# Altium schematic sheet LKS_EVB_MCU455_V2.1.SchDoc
size A3; SheetNumber: 1; SheetTotal: 1
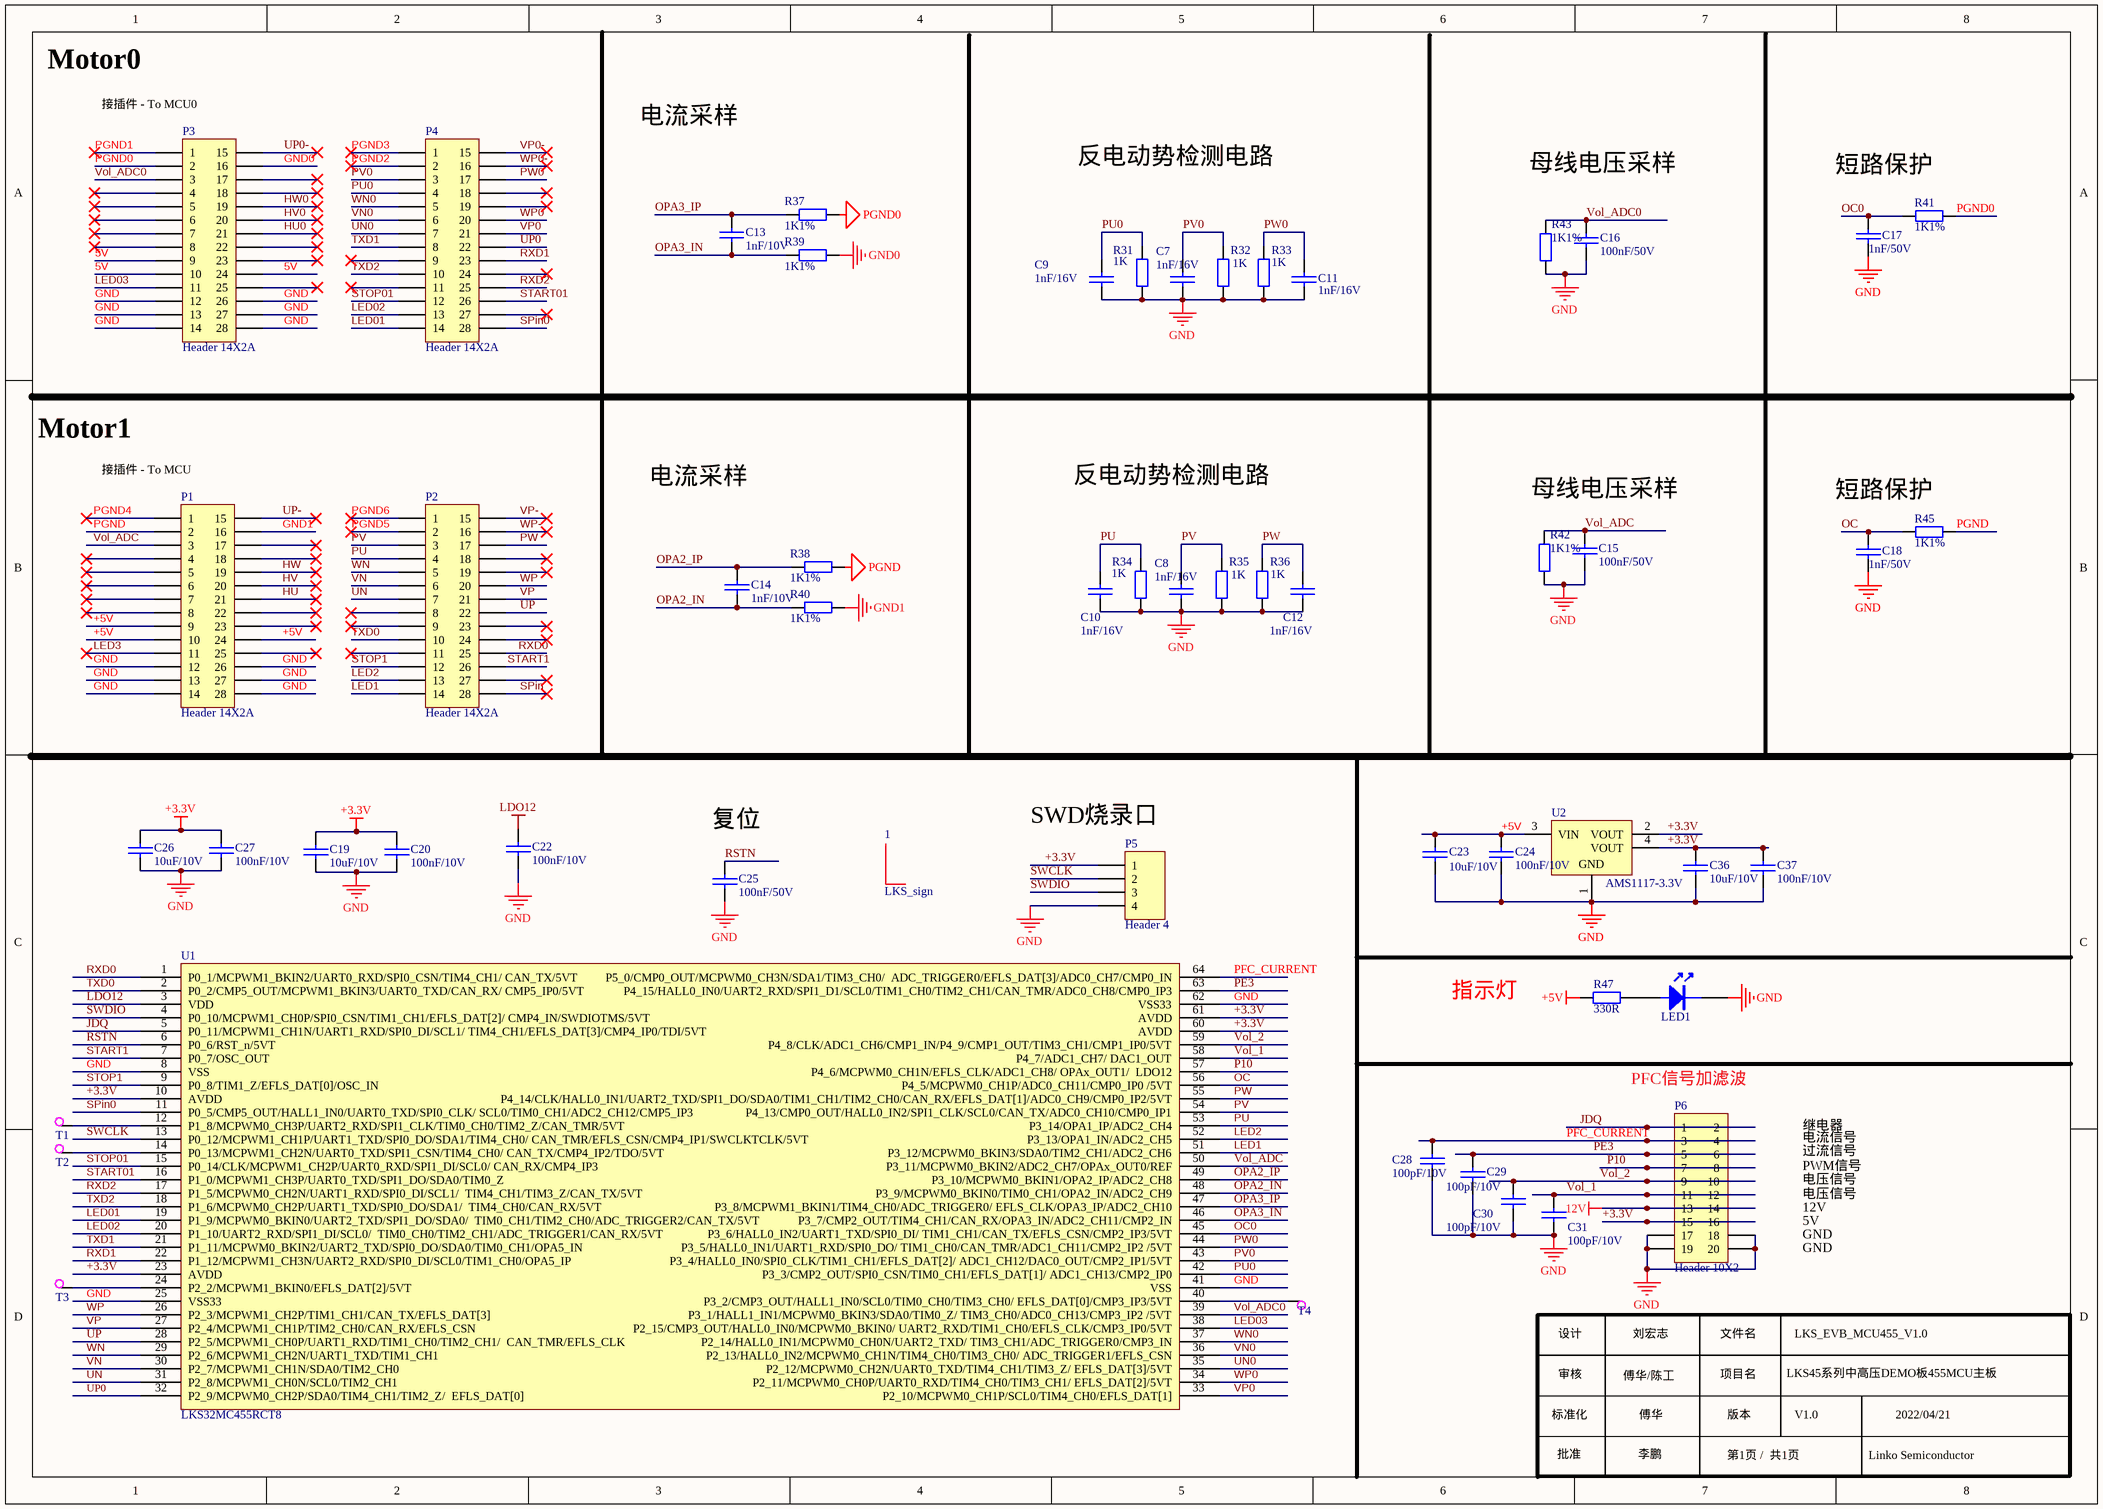
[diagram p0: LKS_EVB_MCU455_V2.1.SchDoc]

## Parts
1  LKS_sign  [LKS_LOGO2]
C7  1nF/16V  [0603C]
C8  1nF/16V  [0603C]
C9  1nF/16V  [0603C]
C10  1nF/16V  [0603C]
C11  1nF/16V  [0603C]
C12  1nF/16V  [0603C]
C13  1nF/10V  [0603C]
C14  1nF/10V  [0603C]
C15  100nF/50V  [0603C]
C16  100nF/50V  [0603C]
C17  1nF/50V  [0603C]
C18  1nF/50V  [0603C]
C19  10uF/10V  [0603C]
C20  100nF/10V  [0603C]
C22  100nF/10V  [0603C]
C23  10uF/10V  [0603C]
C24  100nF/10V  [0603C]
C25  100nF/50V  [0603C]
C26  10uF/10V  [0603C]
C27  100nF/10V  [0603C]
C28  100pF/10V  [0603C]
C29  100pF/10V  [0603C]
C30  100pF/10V  [0603C]
C31  100pF/10V  [0603C]
C36  10uF/10V  [0603C]
C37  100nF/10V  [0603C]
LED1  LED  [LED_0805R]  (value not drawn)
P1  Header 14X2A  [HDR2X14_CEN]
P2  Header 14X2A  [HDR2X14_CEN]
P3  Header 14X2A  [HDR2X14_CEN]
P4  Header 14X2A  [HDR2X14_CEN]
P5  Header 4  [HDR1X4]
P6  Header 10X2  [HDR2X10]
R31  1K  [0603R]
R32  1K  [0603R]
R33  1K  [0603R]
R34  1K  [0603R]
R35  1K  [0603R]
R36  1K  [0603R]
R37  1K1%  [0603R]
R38  1K1%  [0603R]
R39  1K1%  [0603R]
R40  1K1%  [0603R]
R41  1K1%  [0603R]
R42  1K1%  [0603R]
R43  1K1%  [0603R]
R45  1K1%  [0603R]
R47  330R  [0603R]
T1  TestP  [TP-40]  (value not drawn)
T2  TestP  [TP-40]  (value not drawn)
T3  TestP  [TP-40]  (value not drawn)
T4  TestP  [TP-40]  (value not drawn)
U1  LKS32MC455RCT8  [LQFP64]
U2  AMS1117-3.3V  [DCY0004A_M]

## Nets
12V: P6.13 P6.14
+3.3V: C19.1 C20.1 C26.1 C27.1 C36.1 C37.1 P5.1 P6.15 P6.16 U1.10(AVDD) U1.23(AVDD) U1.60(AVDD) U1.61(AVDD) U2.2(VOUT) U2.4(VOUT)
+5V: C23.1 C24.1 P1.9 P1.10 P1.24 R47.1 U2.3(VIN)
GND: C7.2 C8.2 C9.2 C10.2 C11.2 C12.2 C15.1 C16.1 C17.1 C18.1 C19.2 C20.2 C22.2 C23.2 C24.2 C25.2 C26.2 C27.2 C28.2 C29.2 C30.2 C31.2 C36.2 C37.2 LED1.2(K) P1.12 P1.13 P1.14 P1.26 P1.27 P1.28 P3.12 P3.13 P3.14 P3.26 P3.27 P3.28 P5.4 P6.17 P6.18 P6.19 P6.20 R31.2 R32.2 R33.2 R34.2 R35.2 R36.2 R42.1 R43.1 U1.8(VSS) U1.25(VSS33) U1.41(VSS) U1.62(VSS33) U2.1(GND)
GND0: P3.16 R39.1
GND1: P1.16 R40.1
LDO12: C22.1 U1.3(VDD)
PGND: P1.2 R38.1 R45.2
PGND0: P3.2 R37.1 R41.2
5V: P3.9 P3.10 P3.24
HU: P1.21
HU0: P3.21
HV: P1.20
HV0: P3.20
HW: P1.19
HW0: P3.19
JDQ: P6.1 P6.2 U1.5(P0_11/MCPWM1_CH1N/UART1_RXD/SPI0_DI/SCL1/_TIM4_CH1/EFLS_DAT[3]/CMP4_IP0/TDI/5VT)
LED01: P4.14 U1.19(P1_9/MCPWM0_BKIN0/UART2_TXD/SPI1_DO/SDA0/__TIM0_CH1/TIM2_CH0/ADC_TRIGGER2/CAN_TX/5VT)
LED1: P2.14 U1.51(P3_12/MCPWM0_BKIN3/SDA0/TIM2_CH1/ADC2_CH6)
LED02: P4.13 U1.20(P1_10/UART2_RXD/SPI1_DI/SCL0/__TIM0_CH0/TIM2_CH1/ADC_TRIGGER1/CAN_RX/5VT)
LED2: P2.13 U1.52(P3_13/OPA1_IN/ADC2_CH5)
LED03: P3.11 U1.38(P2_15/CMP3_OUT/HALL0_IN0/MCPWM0_BKIN0/_UART2_RXD/TIM1_CH0/EFLS_CLK/CMP3_IP0/5VT)
LED3: P1.11
OC: C18.2 R45.1 U1.56(P4_5/MCPWM0_CH1P/ADC0_CH11/CMP0_IP0_/5VT)
OC0: C17.2 R41.1 U1.45(P3_6/HALL0_IN2/UART1_TXD/SPI0_DI/_TIM1_CH1/CAN_TX/EFLS_CSN/CMP2_IP3/5VT)
OPA2_IN: C14.2 R40.2 U1.48(P3_9/MCPWM0_BKIN0/TIM0_CH1/OPA2_IN/ADC2_CH9)
OPA2_IP: C14.1 R38.2 U1.49(P3_10/MCPWM0_BKIN1/OPA2_IP/ADC2_CH8)
OPA3_IN: C13.2 R39.2 U1.46(P3_7/CMP2_OUT/TIM4_CH1/CAN_RX/OPA3_IN/ADC2_CH11/CMP2_IN)
OPA3_IP: C13.1 R37.2 U1.47(P3_8/MCPWM1_BKIN1/TIM4_CH0/ADC_TRIGGER0/_EFLS_CLK/OPA3_IP/ADC2_CH10)
P10: P6.7 P6.8 U1.57(P4_6/MCPWM0_CH1N/EFLS_CLK/ADC1_CH8/_OPAx_OUT1/__LDO12)
PE3: C29.1 P6.5 P6.6 U1.63(P4_15/HALL0_IN0/UART2_RXD/SPI1_D1/SCL0/TIM1_CH0/TIM2_CH1/CAN_TMR/ADC0_CH8/CMP0_IP3)
PFC_CURRENT: C28.1 P6.3 P6.4 U1.64(P5_0/CMP0_OUT/MCPWM0_CH3N/SDA1/TIM3_CH0/__ADC_TRIGGER0/EFLS_DAT[3]/ADC0_CH7/CMP0_IN)
PGND1: P3.1
PGND2: P4.2
PGND3: P4.1
PGND4: P1.1
PGND5: P2.2
PGND6: P2.1
PU: C10.1 P2.4 R34.1 U1.53(P3_14/OPA1_IP/ADC2_CH4)
PU0: C9.1 P4.4 R31.1 U1.42(P3_3/CMP2_OUT/SPI0_CSN/TIM0_CH1/EFLS_DAT[1]/_ADC1_CH13/CMP2_IP0)
PV: C8.1 P2.3 R35.1 U1.54(P4_13/CMP0_OUT/HALL0_IN2/SPI1_CLK/SCL0/CAN_TX/ADC0_CH10/CMP0_IP1)
PV0: C7.1 P4.3 R32.1 U1.43(P3_4/HALL0_IN0/SPI0_CLK/TIM1_CH1/EFLS_DAT[2]/_ADC1_CH12/DAC0_OUT/CMP2_IP1/5VT)
PW: C12.1 P2.17 R36.1 U1.55(P4_14/CLK/HALL0_IN1/UART2_TXD/SPI1_DO/SDA0/TIM1_CH1/TIM2_CH0/CAN_RX/EFLS_DAT[1]/ADC0_CH9/CMP0_IP2/5VT)
PW0: C11.1 P4.17 R33.1 U1.44(P3_5/HALL0_IN1/UART1_RXD/SPI0_DO/_TIM1_CH0/CAN_TMR/ADC1_CH11/CMP2_IP2_/5VT)
RSTN: C25.1 U1.6(P0_6/RST_n/5VT)
RXD0: P2.25 U1.1(P0_1/MCPWM1_BKIN2/UART0_RXD/SPI0_CSN/TIM4_CH1/_CAN_TX/5VT)
RXD1: P4.23 U1.22(P1_12/MCPWM1_CH3N/UART2_RXD/SPI0_DI/SCL0/TIM1_CH0/OPA5_IP)
RXD2: P4.25 U1.17(P1_5/MCPWM0_CH2N/UART1_RXD/SPI0_DI/SCL1/__TIM4_CH1/TIM3_Z/CAN_TX/5VT)
SPin: P2.28
SPin0: P4.28 U1.11(P0_5/CMP5_OUT/HALL1_IN0/UART0_TXD/SPI0_CLK/_SCL0/TIM0_CH1/ADC2_CH12/CMP5_IP3)
START01: P4.26 U1.16(P1_0/MCPWM1_CH3P/UART0_TXD/SPI1_DO/SDA0/TIM0_Z)
START1: P2.26 U1.7(P0_7/OSC_OUT)
STOP01: P4.12 U1.15(P0_14/CLK/MCPWM1_CH2P/UART0_RXD/SPI1_DI/SCL0/_CAN_RX/CMP4_IP3)
STOP1: P2.12 U1.9(P0_8/TIM1_Z/EFLS_DAT[0]/OSC_IN)
SWCLK: P5.2 U1.13(P0_12/MCPWM1_CH1P/UART1_TXD/SPI0_DO/SDA1/TIM4_CH0/_CAN_TMR/EFLS_CSN/CMP4_IP1/SWCLKTCLK/5VT)
SWDIO: P5.3 U1.4(P0_10/MCPWM1_CH0P/SPI0_CSN/TIM1_CH1/EFLS_DAT[2]/_CMP4_IN/SWDIOTMS/5VT)
TXD0: P2.10 U1.2(P0_2/CMP5_OUT/MCPWM1_BKIN3/UART0_TXD/CAN_RX/_CMP5_IP0/5VT)
TXD1: P4.8 U1.21(P1_11/MCPWM0_BKIN2/UART2_TXD/SPI0_DO/SDA0/TIM0_CH1/OPA5_IN)
TXD2: P4.10 U1.18(P1_6/MCPWM0_CH2P/UART1_TXD/SPI0_DO/SDA1/__TIM4_CH0/CAN_RX/5VT)
UN: P2.7 U1.31(P2_8/MCPWM1_CH0N/SCL0/TIM2_CH1)
UN0: P4.7 U1.35(P2_12/MCPWM0_CH2N/UART0_TXD/TIM4_CH1/TIM3_Z/_EFLS_DAT[3]/5VT)
UP: P2.22 U1.28(P2_5/MCPWM1_CH0P/UART1_RXD/TIM1_CH0/TIM2_CH1/__CAN_TMR/EFLS_CLK)
UP0: P4.22 U1.32(P2_9/MCPWM0_CH2P/SDA0/TIM4_CH1/TIM2_Z/__EFLS_DAT[0])
UP0-: P3.15
UP-: P1.15
VN: P2.6 U1.30(P2_7/MCPWM1_CH1N/SDA0/TIM2_CH0)
VN0: P4.6 U1.36(P2_13/HALL0_IN2/MCPWM0_CH1N/TIM4_CH0/TIM3_CH0/_ADC_TRIGGER1/EFLS_CSN)
Vol_1: C31.1 P6.11 P6.12 U1.58(P4_7/ADC1_CH7/_DAC1_OUT)
Vol_2: C30.1 P6.9 P6.10 U1.59(P4_8/CLK/ADC1_CH6/CMP1_IN/P4_9/CMP1_OUT/TIM3_CH1/CMP1_IP0/5VT)
Vol_ADC: C15.2 P1.3 R42.2 U1.50(P3_11/MCPWM0_BKIN2/ADC2_CH7/OPAx_OUT0/REF)
Vol_ADC0: C16.2 P3.3 R43.2 U1.39(P3_1/HALL1_IN1/MCPWM0_BKIN3/SDA0/TIM0_Z/_TIM3_CH0/ADC0_CH13/CMP3_IP2_/5VT)
VP: P2.21 U1.27(P2_4/MCPWM1_CH1P/TIM2_CH0/CAN_RX/EFLS_CSN)
VP0: P4.21 U1.33(P2_10/MCPWM0_CH1P/SCL0/TIM4_CH0/EFLS_DAT[1])
VP0-: P4.15
VP-: P2.15
WN: P2.5 U1.29(P2_6/MCPWM1_CH2N/UART1_TXD/TIM1_CH1)
WN0: P4.5 U1.37(P2_14/HALL0_IN1/MCPWM0_CH0N/UART2_TXD/_TIM3_CH1/ADC_TRIGGER0/CMP3_IN)
WP: P2.20 U1.26(P2_3/MCPWM1_CH2P/TIM1_CH1/CAN_TX/EFLS_DAT[3])
WP0: P4.20 U1.34(P2_11/MCPWM0_CH0P/UART0_RXD/TIM4_CH0/TIM3_CH1/_EFLS_DAT[2]/5VT)
WP0-: P4.16
WP-: P2.16
NetLED1_1: LED1.1(A) R47.2
NetT1_1: T1.1 U1.12(P1_8/MCPWM0_CH3P/UART2_RXD/SPI1_CLK/TIM0_CH0/TIM2_Z/CAN_TMR/5VT)
NetT2_1: T2.1 U1.14(P0_13/MCPWM1_CH2N/UART0_TXD/SPI1_CSN/TIM4_CH0/_CAN_TX/CMP4_IP2/TDO/5VT)
NetT3_1: T3.1 U1.24(P2_2/MCPWM1_BKIN0/EFLS_DAT[2]/5VT)
NetT4_1: T4.1 U1.40(P3_2/CMP3_OUT/HALL1_IN0/SCL0/TIM0_CH0/TIM3_CH0/_EFLS_DAT[0]/CMP3_IP3/5VT)

Not connected (* = marked no-connect by the designer): P1 4* 5* 6* 7* 8* 17* 18* 22* 23* 25*; P2 8* 9* 11* 18* 19* 23* 24* 27*; P3 4* 5* 6* 7* 8* 17* 18* 22* 23* 25*; P4 9* 11* 18* 19* 24* 27*

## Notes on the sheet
- Motor0
- (near P3) 接插件 - To MCU0
- 电流采样
- 反电动势检测电路
- 母线电压采样
- 短路保护
- Motor1
- (near P1) 接插件 - To MCU
- (near C25) 复位
- (near P5) SWD烧录口
- 指示灯
- (near P6) PFC信号加滤波
- 电压信号
- 继电器
- 电流信号
- 过流信号
- PWM信号
- 5V
- 12V
- GND
- 设计
- 审核
- 傅华/陈工
- 刘宏志
- 文件名
- 项目名
- LKS45系列中高压DEMO板455MCU主板
- LKS_EVB_MCU455_V1.0
- 标准化
- 批准
- 李鹏
- 傅华
- 版本
- 第1页 /  共1页
- V1.0
- Linko Semiconductor
- 2022/04/21

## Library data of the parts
C7-C12 = CAP: Capacitor
C13-C20 C22-C31 C36 C37 = C: Capacitor
LED1 = LED: LED_Light
P1-P4 = Header 14X2A: Header, 14-Pin, Dual row
P5 = Header 4: Header, 4-Pin
P6 = Header 10X2: Header, 10-Pin, Dual row
R31-R43 R45 = Res: Resistor; Value: K
R47 = Res: Resistor; Value: 330
T1-T4 = TestP: 测试点
U1 = LKS32MC455RCT8: 芯片
U2 = CMP-019-00008-2: Low-Dropout Linear Regulator, 1 A, 3.3 V, 0 to 125 degC, 4-Pin SOT223 (DCY), RoHS, Tape and Reel; Manufacturer: Texas Instruments; Output Voltage: 3.3V; Dropout Voltage: 1.2V; Max Ouput Current: 1A; Min Input Voltage: 2.5V; Nominal Supply Current: 5mA; Outputs: 1; Max Input Voltage: 15V; Min Supply Voltage: 3.2V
